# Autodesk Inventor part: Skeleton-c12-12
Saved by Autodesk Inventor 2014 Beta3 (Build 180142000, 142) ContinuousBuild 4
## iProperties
Created: 2011-01
Part Number: Skeleton-c12-12
Material: Generic
Document SubType Name: Modeling
Designer: Thom Tremblay
Density: 1 g/cm^3
Appearance: Generic
_SkeletonDoc: Frame Skeleton File
_Version: 15.0.0
Author: Thom Tremblay
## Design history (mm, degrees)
sketch "Reference Skeleton"
  geometry: L1 through (404.523, 1164.395) direction (1, 0); L2 through (325.691, 1070.446) direction (1, 0); 34 other entities
  constraints: 10 horizontal
